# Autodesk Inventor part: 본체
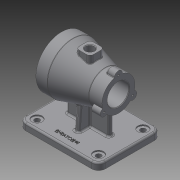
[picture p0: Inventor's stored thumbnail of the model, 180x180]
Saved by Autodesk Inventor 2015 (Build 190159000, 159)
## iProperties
Created: 2021-10
Part Number: 본체
Material: 일반
Document SubType Name: Modeling
Designer: 1016549
Density: 1 g/cm^3
Appearance: 기본값
Author: 1016549
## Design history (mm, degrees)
sketch "스케치1"
  geometry: L1 (70, 55)-(-70, 55); L2 (-70, 55)-(-70, -55); L3 (-70, -55)-(70, -55); L4 (70, -55)-(70, 55); L5 (70, 55)-(-70, -55); L6 (-70, 55)-(70, -55); 1 further point
  constraints: 12 end point, 2 midpoint, 2 parallel, 1 horizontal, 1 perpendicular
  dimensions: "d0" = 110 distance of L3.end L1.start; "d1" = 140 distance of L2.end L3.end
extrude "돌출1" new body sketch "스케치1" distance "d2" = 12; taper "d3" = 0 deg
fillet "모깎기1" dims "d4" = 12
sketch "스케치3"
  geometry: L1 (70, 0)-(-70, 0) reference; L2 (-70, 0)-(-70, 12) reference; L3 (-70, 12)-(70, 12) reference; L4 (70, 12)-(70, 0) reference; L5 (50, 127)-(30, 127); L6 (-50, 111)-(-50, 82); L7 (-50, 82)-(50, 82); L8 (50, 82)-(50, 127); L9 (30, 127)-(-27, 111); L10 (-27, 111)-(-50, 111); 3 further points
  constraints: 12 end point, 2 horizontal, 2 midpoint, 2 parallel, 1 perpendicular, 1 vertical alignment
  dimensions: "d13" = 82 distance between parallel lines of L1 L7; "d14" = 20 distance from line of L5.end L8; "d15" = 23 distance from line of L6 L9.end; "d16" = 90 diameter of L5 L7; "d17" = 58 diameter of L10 L7; "d18" = 100 distance between parallel lines of L6 L8
revolve "회전1" sketch "스케치3" stored, may be unused: angle "d19" = 90 deg
sketch "스케치4"
  geometry: L1 (37, 4)-(-37, 4); L2 (-37, 4)-(-37, -4); L3 (-37, -4)-(37, -4); L4 (37, -4)-(37, 4); L5 (37, 4)-(-37, -4); L6 (-37, 4)-(37, -4); L7 (-4, 24)-(4, 24); L8 (4, 24)-(4, -24); L9 (4, -24)-(-4, -24); L10 (-4, -24)-(-4, 24); L11 (-4, 24)-(4, -24); L12 (4, 24)-(-4, -24); 2 further points
  constraints: 24 end point, 6 midpoint, 4 parallel, 2 horizontal, 2 perpendicular
  dimensions: "d20" = 8 distance of L3.end L1.start; "d21" = 74 distance of L1.start L1.end; "d22" = 8 distance of L7.start L7.end; "d23" = 48 distance of L7.end L8.end
extrude "돌출2" join sketch "스케치4" distance "d24" = 70; taper "d25" = 0 deg
feature "면 기울기1" dims angle "d26" = 5 deg
fillet "모깎기2" dims "d27" = 3
fillet "모깎기3" dims "d28" = 3
sketch "스케치6"
  geometry: C1 r 7 at (-29, 0); 2 further points
  constraints: 1 centre point, 1 horizontal alignment, 1 other
  dimensions: "d32" = 7 radius of C1
extrude "돌출4" join sketch "스케치6" distance "d33" = 15; taper "d34" = 0 deg
node "작업 평면1"
sketch "스케치7"
  geometry: L1 (-34, -4)-(-30, -4) reference; L2 (-30, -4)-(-30, 4) reference; L3 (-30, 4)-(-34, 4) reference; L4 (-37, 1)-(-37, -1) reference; L5 (-50, 45)-(-50, -45) reference; L6 (-4, -7)-(-4, -17.773) reference; L7 (4, -17.559)-(4, -7) reference; L8 (7, -4)-(27, -4) reference; L9 (27, -4)-(27, 4) reference; L10 (27, 4)-(7, 4) reference; L11 (4, 7)-(4, 17.559) reference; L12 (-4, 17.773)-(-4, 7) reference; L13 (-7, 4)-(-30, 4) reference; L14 (-30, -4)-(-30, 4) reference; L15 (-30, -4)-(-7, -4) reference; L16 (27, 29)-(-30, 45) reference; L17 (27, -29)-(-30, -45) reference; L18 (12.5, -12.5)-(-12.5, -12.5); L19 (-12.5, -12.5)-(-12.5, 12.5); L20 (-12.5, 12.5)-(12.5, 12.5); L21 (12.5, 12.5)-(12.5, -12.5); L22 (12.5, -12.5)-(-12.5, 12.5); L23 (-12.5, -12.5)-(12.5, 12.5); 5 further points
  constraints: 12 end point, 2 midpoint, 2 parallel, 1 horizontal, 1 perpendicular, 12 other
  dimensions: "d39" = 25 distance of L20.end L18.start; "d40" = 25 distance of L18.start L18.end
extrude "돌출5" join sketch "스케치7" stored distance "d41" = 15; taper "d42" = 0 deg
fillet "모깎기4" dims "d43" = 6
fillet "모깎기5" dims "d44" = 3
fillet "모깎기6" dims "d45" = 1
sketch "스케치8"
  geometry: C1 r 45 at (0, 0) reference; 1 further point
hole "구멍2" sketch "스케치8" at (0, 0) diameter "d46" = 62; stored, may be unused: countersink angle "d50" = 90 deg, drill point angle "d52" = 0 deg; dims "d47" = 6, "d48" = 62, "d49" = 23, "d51" = 23
sketch "스케치9"
  geometry: C1 r 31 at (0, 0) reference; 1 further point
hole "구멍3" sketch "스케치9" at (0, 0) diameter "d53" = 50; stored, may be unused: countersink angle "d57" = 90 deg, drill point angle "d59" = 0 deg; dims "d54" = 6, "d55" = 62, "d56" = 23, "d58" = 47
sketch "스케치10"
  geometry: A1 r 29 centre (29, 0) between (49.095, -20.909) and (49.095, 20.909) reference; 1 further point
hole "구멍4" sketch "스케치10" at (29, 0) diameter "d60" = 38; stored, may be unused: countersink angle "d64" = 90 deg, drill point angle "d66" = 0 deg; dims "d61" = 6, "d62" = 62, "d63" = 23, "d65" = 30
sketch "스케치11"
  geometry: C1 r 31 at (0, 0) reference; 2 further points
  constraints: 1 horizontal alignment
  dimensions: "d67" = 40 distance of C1.centre point (40, 0)
hole "구멍5" sketch "스케치11" at (40, 0) diameter "d68" = 3.242; stored, may be unused: countersink angle "d72" = 90 deg, drill point angle "d74" = 118 deg; dims "d69" = 9, "d70" = 62, "d71" = 23, "d73" = 11
sketch "스케치12"
  geometry: A1 r 7 centre (43.5, 25.115) between (49.095, 20.909) and (37.06, 27.858) reference; A2 r 7 centre (0, 0) between (0.845, 6.949) and (0.845, -6.949) reference; A3 r 7 centre (43.5, -25.115) between (37.06, -27.858) and (49.095, -20.909) reference; 2 further points
hole "구멍6" sketch "스케치12" at (40.806, 124.368), (0, 0), (43.5, -25.115), (43.5, 25.115) diameter "d78" = 3.242; stored, may be unused: countersink angle "d82" = 90 deg, drill point angle "d84" = 118 deg; dims "d79" = 9, "d80" = 62, "d81" = 23, "d83" = 11
sketch "스케치13"
  geometry: 1 further point
hole "구멍7" sketch "스케치13" at (0, 0) diameter "d85" = 15; stored, may be unused: countersink angle "d89" = 90 deg, drill point angle "d91" = 118 deg; dims "d86" = 9, "d87" = 62, "d88" = 23, "d90" = 20
fillet "모깎기7" dims "d92" = 3
fillet "모깎기8" dims "d93" = 1
sketch "스케치14"
  geometry: L1 (-58, -55)-(58, -55) reference; 2 further points
  constraints: 1 vertical alignment, 1 other
  dimensions: "d94" = 15 distance from line of L1 point (0, -40)
feature "엠보싱1" sketch "스케치14" dims "d17" = 58, "d95" = 0.5, "d96" = 0
fillet "모깎기9" dims "d97" = 3
fillet "모깎기10" dims "d98" = 3
fillet "모깎기11" dims "d99" = 3
chamfer "모따기1" distance "d100" = 1; stored, may be unused: second distance "d101" = 2, angle "d102" = 45 deg
chamfer "모따기2" distance "d103" = 1; stored, may be unused: second distance "d104" = 2, angle "d105" = 45 deg
sketch "스케치15"
  geometry: L1 (58, 55)-(-58, 55) reference; L2 (-70, 43)-(-70, -43) reference; 2 further points
  dimensions: "d106" = 16 distance from line of point (-54, 39) L1; "d107" = 16 distance from line of point (-54, 39) L2
hole "구멍8" sketch "스케치15" at (-54, 39) diameter "d108" = 9; stored, may be unused: countersink angle "d112" = 90 deg, drill point angle "d114" = 118 deg; dims "d109" = 9, "d110" = 18, "d111" = 2, "d113" = 20
node "솔리드1"
pattern_circular "원형 패턴1" dims angle "d36" = 360 deg
pattern_circular "원형 패턴2" dims angle "d76" = 360 deg
pattern_linear "직사각형 패턴1" dims "d117" = 108
pattern_linear "직사각형 패턴2" dims "d120" = 78
node "투영된 루프1"
node "투영된 루프2"
node "절단 모서리 투영1"
other parameters: "d38" = 127
